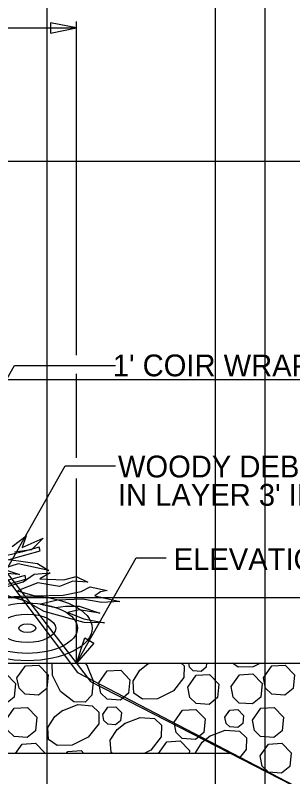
# Model space of a CAD drawing. Extents: x 1578769 to 1579225, y 724002 to 724828.
# Drawn here: x 1578887.04 to 1578893.4, y 724532.87 to 724550.33 of the extents above; entities that cross this region are included whole.
import ezdxf

# ---------------------------------------------------------------- set-up
doc = ezdxf.new("R2010")
doc.units = 0
for name, color, linetype in [('1', 7, 'Continuous'), ('Default', 7, 'Continuous'), ('G-ANNO-SYMB', 7, 'Continuous'), ('Old_Level_1', 7, 'Continuous'), ('Old_Level_41', 7, 'Continuous'), ('R_Exist Surface', 7, 'Continuous'), ('R_Fin Surface', 7, 'Continuous'), ('R_Rip-Rap', 7, 'Continuous')]:
    doc.layers.add(name, color=color, linetype=linetype)

msp = doc.modelspace()

# ---------------------------------------------------------------- linework, layer by layer
at = {"layer": '1'}
for p, q in [((1578873.274, 724550.034), (1578888.441, 724550.034)), ((1578888.441, 724542.535), (1578888.441, 724550.185)), ((1578888.441, 724540.18), (1578888.441, 724542.109)), ((1578888.441, 724535.476), (1578888.441, 724539.707))]:
    msp.add_line(p, q, dxfattribs=at)
for points in [[(1578887.841, 724549.914), (1578888.441, 724550.034), (1578887.841, 724550.154)], [(1578888.841, 724535.939), (1578888.441, 724535.476), (1578888.633, 724536.057)]]:
    msp.add_lwpolyline(points, close=True, dxfattribs=at)
for points in [[(1578885.381, 724539.411), (1578887.02, 724542.302), (1578889.334, 724542.302)], [(1578886.561, 724537.143), (1578888.18, 724539.999), (1578889.334, 724539.999)], [(1578888.441, 724535.476), (1578889.809, 724537.89), (1578890.495, 724537.89)]]:
    msp.add_lwpolyline(points, dxfattribs=at)
at = {"layer": 'Default'}
msp.add_line((1578891.62, 724578.446), (1578891.62, 724328.446), dxfattribs=at)
msp.add_lwpolyline([(1578827.766, 724545.778), (1578841.746, 724545.874), (1578855.126, 724545.979), (1578880.286, 724546.165), (1578882.476, 724543.201), (1578888.466, 724535.266), (1578896.646, 724531.004), (1578897.956, 724530.207), (1578900.066, 724530.294), (1578933.126, 724531.692), (1578958.306, 724535.052), (1578969.886, 724536.54), (1578983.926, 724537.607), (1579000.856, 724538.888), (1579028.426, 724540.267), (1579057.456, 724541.791), (1579058.756, 724541.812)], dxfattribs=at)
at = {"layer": 'G-ANNO-SYMB'}
for points in [[(1578882.678, 724537.23), (1578883.733, 724537.32), (1578884.316, 724537.44), (1578885.112, 724537.646), (1578885.714, 724537.68), (1578886.346, 724537.716), (1578886.951, 724537.867), (1578887.607, 724538.05), (1578887.587, 724538.136), (1578887.205, 724538.027), (1578886.625, 724537.892), (1578886.128, 724537.777), (1578886.312, 724537.991), (1578886.853, 724538.167), (1578886.537, 724538.149), (1578886.133, 724538.009), (1578885.994, 724537.856), (1578885.602, 724537.79), (1578884.942, 724537.752), (1578884.344, 724537.573), (1578883.315, 724537.368), (1578882.623, 724537.343)], [(1578882.328, 724536.611), (1578883.386, 724536.694), (1578883.972, 724536.81), (1578884.773, 724537.011), (1578885.376, 724537.041), (1578886.008, 724537.073), (1578886.617, 724537.22), (1578887.278, 724537.399), (1578887.26, 724537.485), (1578886.875, 724537.379), (1578886.292, 724537.247), (1578885.793, 724537.135), (1578885.982, 724537.348), (1578886.527, 724537.521), (1578886.211, 724537.504), (1578885.803, 724537.368), (1578885.66, 724537.215), (1578885.267, 724537.152), (1578884.606, 724537.118), (1578884.003, 724536.943), (1578882.969, 724536.745), (1578882.276, 724536.724)]]:
    msp.add_lwpolyline(points, close=True, dxfattribs=at)
at = {"layer": 'Old_Level_1'}
for p, q in [((1578886.963, 724538.151), (1578887.289, 724538.392)), ((1578887.289, 724538.392), (1578887.197, 724538.13)), ((1578887.197, 724538.13), (1578887.675, 724538.341)), ((1578887.675, 724538.341), (1578887.406, 724538.078)), ((1578887.406, 724538.078), (1578887.017, 724538.022)), ((1578886.891, 724537.854), (1578887.543, 724537.764)), ((1578887.101, 724537.752), (1578886.74, 724537.639)), ((1578886.74, 724537.639), (1578887.132, 724537.507)), ((1578887.807, 724537.601), (1578887.101, 724537.752)), ((1578887.543, 724537.764), (1578887.807, 724537.601)), ((1578887.132, 724537.507), (1578886.38, 724537.562)), ((1578887.214, 724537.339), (1578887.471, 724537.519)), ((1578887.471, 724537.519), (1578887.834, 724537.545)), ((1578887.834, 724537.545), (1578887.603, 724537.412)), ((1578888.15, 724537.391), (1578888.434, 724537.463)), ((1578888.434, 724537.463), (1578888.698, 724537.335)), ((1578886.801, 724537.218), (1578887.214, 724537.339)), ((1578887.553, 724537.318), (1578887.089, 724537.136)), ((1578888.049, 724537.236), (1578887.553, 724537.318)), ((1578887.603, 724537.412), (1578888.15, 724537.391)), ((1578888.358, 724537.356), (1578888.049, 724537.236)), ((1578888.698, 724537.335), (1578888.358, 724537.356)), ((1578887.089, 724537.136), (1578887.482, 724537.021)), ((1578888.132, 724537.033), (1578888.546, 724537.12)), ((1578888.546, 724537.12), (1578888.752, 724537.223)), ((1578888.752, 724537.223), (1578889.144, 724537.142)), ((1578888.988, 724537.116), (1578888.86, 724537.017)), ((1578889.144, 724537.142), (1578888.988, 724537.116)), ((1578887.276, 724536.901), (1578886.726, 724537.059)), ((1578887.482, 724537.021), (1578888.132, 724537.033)), ((1578888.576, 724536.943), (1578888.004, 724536.918)), ((1578889.019, 724536.87), (1578888.576, 724536.943)), ((1578888.86, 724537.017), (1578889.436, 724536.888)), ((1578887.697, 724536.66), (1578887.276, 724536.901)), ((1578888.004, 724536.918), (1578887.616, 724536.828)), ((1578887.616, 724536.828), (1578887.956, 724536.755)), ((1578887.956, 724536.755), (1578888.189, 724536.785)), ((1578888.189, 724536.785), (1578888.502, 724536.785)), ((1578888.502, 724536.785), (1578888.973, 724536.622)), ((1578889.436, 724536.888), (1578889.019, 724536.87)), ((1578888.614, 724536.406), (1578887.697, 724536.66)), ((1578888.503, 724536.699), (1578888.244, 724536.638)), ((1578888.244, 724536.638), (1578888.612, 724536.492)), ((1578888.973, 724536.622), (1578888.503, 724536.699)), ((1578888.612, 724536.492), (1578889.081, 724536.398)), ((1578889.081, 724536.398), (1578888.614, 724536.406))]:
    msp.add_line(p, q, dxfattribs=at)
for major_axis in [(1.486, 0), (1.152, 0), (0.651, 0), (0.197, 0)]:
    msp.add_ellipse((1578887.313, 724536.277), major_axis=major_axis, ratio=0.5, dxfattribs=at)
at = {"layer": 'Old_Level_41'}
for p, q in [((1578887.766, 724526.976), (1578887.766, 724556.976)), ((1578892.766, 724526.976), (1578892.766, 724556.976))]:
    msp.add_line(p, q, dxfattribs=at)
for points in [[(1578927.766, 724546.976), (1578827.766, 724546.976)], [(1578827.766, 724541.976), (1578888.475, 724541.976)], [(1578888.475, 724541.976), (1578927.766, 724541.976)], [(1578927.766, 724536.976), (1578827.766, 724536.976)]]:
    msp.add_lwpolyline(points, dxfattribs=at)
at = {"layer": 'R_Exist Surface'}
msp.add_lwpolyline([(1578827.766, 724545.753), (1578832.87, 724545.829), (1578835.855, 724545.829), (1578849.85, 724545.921), (1578865.935, 724546.072), (1578876.895, 724546.144), (1578879.811, 724546.167), (1578880.852, 724545.469), (1578882.795, 724542.798), (1578885.883, 724538.793), (1578888.763, 724535.059), (1578896.849, 724530.913), (1578897.81, 724530.272), (1578902.771, 724530.386), (1578927.766, 724531.445)], dxfattribs=at)
at = {"layer": 'R_Fin Surface'}
msp.add_lwpolyline([(1578875.273, 724535.476), (1578888.441, 724535.476)], dxfattribs=at)
msp.add_lwpolyline([(1578875.273, 724535.476), (1578888.441, 724535.476)], dxfattribs=at)
at = {"layer": 'R_Rip-Rap'}
for p, q in [((1578883.887, 724535.476), (1578896.998, 724535.476)), ((1578888.642, 724535.476), (1578888.688, 724535.418)), ((1578890.063, 724535.451), (1578890.127, 724535.476)), ((1578891.978, 724533.411), (1578883.887, 724533.411)), ((1578891.978, 724533.411), (1578891.978, 724533.411))]:
    msp.add_line(p, q, dxfattribs=at)
for points in [[(1578887.076, 724535.14), (1578887.268, 724535.413), (1578887.575, 724535.431), (1578887.788, 724535.209), (1578887.757, 724534.9), (1578887.568, 724534.742), (1578887.265, 724534.764), (1578887.123, 724534.902), (1578887.076, 724535.14)], [(1578888.679, 724535.432), (1578888.821, 724535.073), (1578888.793, 724534.743), (1578888.643, 724534.586), (1578888.376, 724534.591), (1578888.071, 724534.829), (1578887.887, 724535.197), (1578887.882, 724535.476)], [(1578890.845, 724535.476), (1578890.909, 724535.415), (1578890.904, 724535.148), (1578890.666, 724534.843), (1578890.298, 724534.659), (1578889.951, 724534.653), (1578889.756, 724534.792), (1578889.738, 724535.068), (1578889.896, 724535.315), (1578890.078, 724535.46)], [(1578891.424, 724535.476), (1578891.415, 724535.385), (1578891.301, 724535.29), (1578891.12, 724535.303), (1578891.034, 724535.386), (1578891.017, 724535.476)], [(1578892.664, 724535.476), (1578892.494, 724535.391), (1578892.147, 724535.385), (1578892.019, 724535.476)], [(1578892.73, 724535.14), (1578892.922, 724535.413), (1578893.228, 724535.431), (1578893.442, 724535.209), (1578893.411, 724534.9), (1578893.221, 724534.742), (1578892.918, 724534.764), (1578892.776, 724534.902), (1578892.73, 724535.14)], [(1578886.331, 724534.939), (1578886.523, 724535.213), (1578886.83, 724535.23), (1578887.043, 724535.009), (1578887.012, 724534.699), (1578886.823, 724534.542), (1578886.52, 724534.564), (1578886.378, 724534.702), (1578886.331, 724534.939)], [(1578888.955, 724535.029), (1578889.147, 724535.303), (1578889.454, 724535.32), (1578889.667, 724535.099), (1578889.636, 724534.789), (1578889.447, 724534.632), (1578889.144, 724534.654), (1578889.002, 724534.792), (1578888.956, 724535.029)], [(1578890.994, 724534.928), (1578891.186, 724535.201), (1578891.492, 724535.219), (1578891.706, 724534.998), (1578891.675, 724534.688), (1578891.485, 724534.53), (1578891.182, 724534.552), (1578891.04, 724534.691), (1578890.994, 724534.928)], [(1578891.985, 724534.939), (1578892.177, 724535.213), (1578892.483, 724535.23), (1578892.697, 724535.009), (1578892.666, 724534.699), (1578892.476, 724534.542), (1578892.173, 724534.564), (1578892.031, 724534.702), (1578891.985, 724534.939)], [(1578888.109, 724534.388), (1578888.468, 724534.53), (1578888.798, 724534.502), (1578888.955, 724534.353), (1578888.95, 724534.085), (1578888.712, 724533.781), (1578888.344, 724533.597), (1578887.997, 724533.591), (1578887.802, 724533.729), (1578887.784, 724534.005), (1578887.942, 724534.253), (1578888.124, 724534.397)], [(1578886.82, 724534.17), (1578887.012, 724534.443), (1578887.319, 724534.46), (1578887.532, 724534.239), (1578887.501, 724533.93), (1578887.312, 724533.772), (1578887.009, 724533.794), (1578886.866, 724533.932), (1578886.82, 724534.17)], [(1578889.043, 724534.303), (1578889.158, 724534.467), (1578889.342, 724534.478), (1578889.47, 724534.345), (1578889.452, 724534.159), (1578889.338, 724534.065), (1578889.156, 724534.078), (1578889.071, 724534.161), (1578889.043, 724534.303)], [(1578890.679, 724534.128), (1578890.871, 724534.401), (1578891.177, 724534.419), (1578891.391, 724534.198), (1578891.36, 724533.888), (1578891.17, 724533.73), (1578890.867, 724533.752), (1578890.725, 724533.891), (1578890.679, 724534.128)], [(1578891.844, 724534.24), (1578891.959, 724534.404), (1578892.143, 724534.415), (1578892.271, 724534.282), (1578892.253, 724534.096), (1578892.139, 724534.002), (1578891.957, 724534.015), (1578891.872, 724534.098), (1578891.844, 724534.24)], [(1578892.474, 724534.17), (1578892.666, 724534.443), (1578892.972, 724534.46), (1578893.185, 724534.239), (1578893.155, 724533.93), (1578892.965, 724533.772), (1578892.662, 724533.794), (1578892.52, 724533.932), (1578892.474, 724534.17)], [(1578889.541, 724534.093), (1578889.9, 724534.235), (1578890.23, 724534.207), (1578890.387, 724534.058), (1578890.382, 724533.79), (1578890.144, 724533.486), (1578889.994, 724533.411)], [(1578889.267, 724533.411), (1578889.234, 724533.434), (1578889.215, 724533.71), (1578889.374, 724533.958), (1578889.555, 724534.102)], [(1578891.168, 724533.411), (1578891.167, 724533.42), (1578891.326, 724533.667), (1578891.507, 724533.812)], [(1578891.493, 724533.803), (1578891.852, 724533.945), (1578892.182, 724533.916), (1578892.339, 724533.767), (1578892.334, 724533.499), (1578892.182, 724533.306)], [(1578887.042, 724533.411), (1578887.193, 724533.625), (1578887.5, 724533.642), (1578887.713, 724533.421), (1578887.712, 724533.411)], [(1578890.321, 724533.411), (1578890.509, 724533.678), (1578890.816, 724533.696), (1578891.029, 724533.475), (1578891.023, 724533.411)], [(1578892.654, 724533.352), (1578892.846, 724533.625), (1578893.153, 724533.642), (1578893.366, 724533.421), (1578893.335, 724533.112), (1578893.146, 724532.954), (1578892.843, 724532.976), (1578892.701, 724533.114), (1578892.654, 724533.352)], [(1578888.21, 724533.411), (1578888.243, 724533.457), (1578888.55, 724533.475), (1578888.612, 724533.411)]]:
    msp.add_lwpolyline(points, dxfattribs=at)

# ---------------------------------------------------------------- texts
at = {"layer": '1'}
for s, p in [("1' COIR WRAPPED SOIL LIFT", (1578889.273, 724542.051)), ('WOODY DEBRIS OF ALL SIZES', (1578889.391, 724539.734)), ("IN LAYER 3' IN HEIGHT", (1578889.391, 724539.083)), ("ELEVATION 283.5'", (1578890.67, 724537.609))]:
    msp.add_text(s, height=0.5, dxfattribs=at).set_placement(p)

doc.saveas('drawing.dxf')
